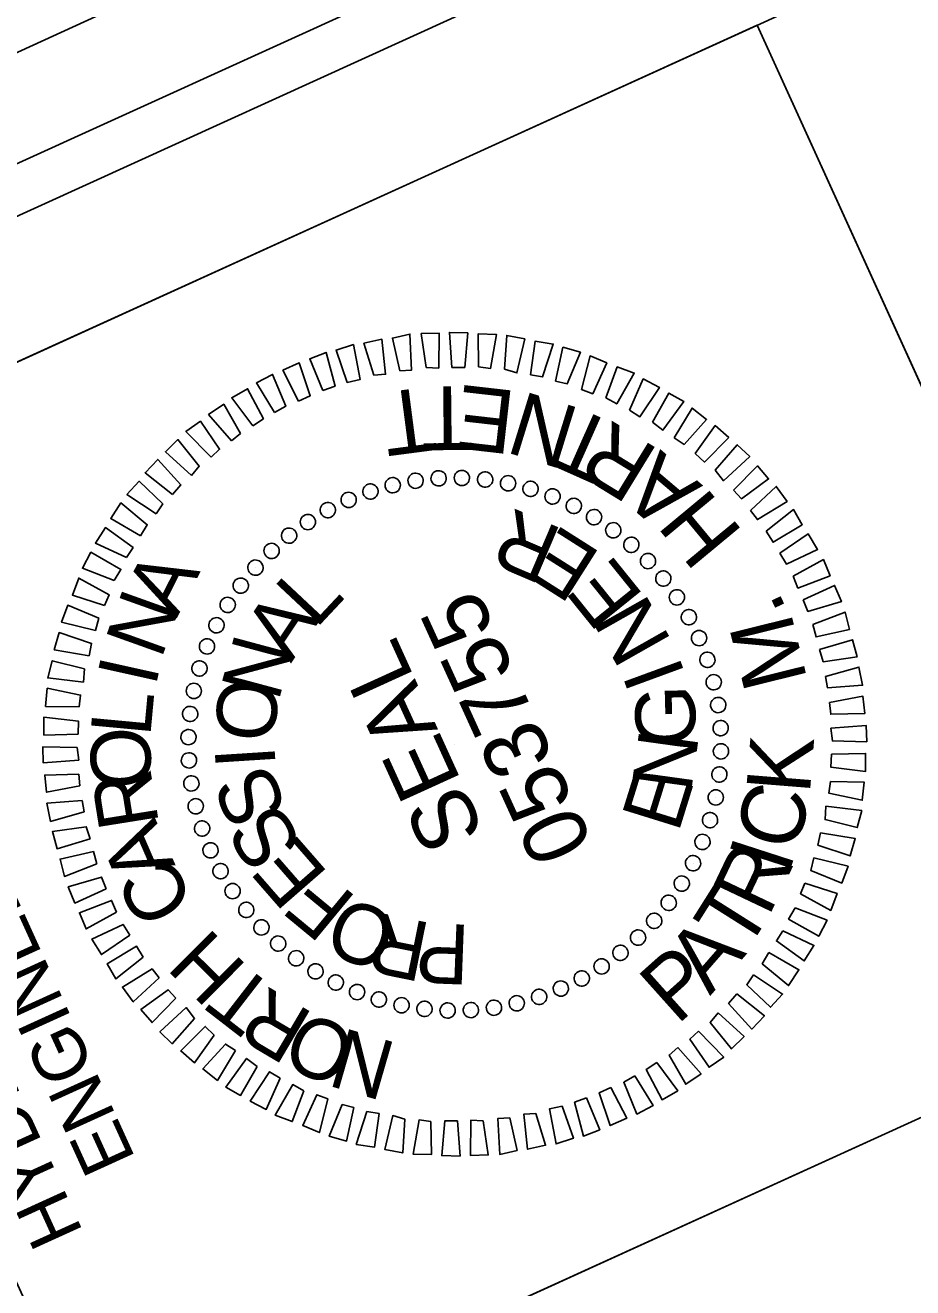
# Model space of a CAD drawing. Extents: x 2097304 to 2099003, y 683920 to 685908.
# Drawn here: x 2097390.4 to 2097474, y 685385.6 to 685504.5 of the extents above; entities that cross this region are included whole.
import ezdxf

# ---------------------------------------------------------------- set-up
doc = ezdxf.new("R2010")
doc.units = 0
for name, color, linetype in [('Sheet PE Seal Cell', 7, 'Continuous'), ('Sheet Plot Border Inside CELL', 7, 'Continuous'), ('Sheet Plot Border Outside CELL', 7, 'Continuous'), ('Sheet Profile CELL', 7, 'Continuous'), ('Sheet Sticker Exception Certification CELL', 7, 'Continuous'), ('Sheet Sticker Incomplete CELL', 7, 'Continuous')]:
    doc.layers.add(name, color=color, linetype=linetype)

msp = doc.modelspace()

# ---------------------------------------------------------------- linework, layer by layer
at = {"layer": 'Sheet PE Seal Cell'}
for p, q in [((2097427.17, 685461.63), (2097427.17, 685461.63)), ((2097429.37, 685461.86), (2097429.37, 685461.86)), ((2097431.56, 685461.87), (2097431.56, 685461.87)), ((2097433.75, 685461.77), (2097433.75, 685461.77)), ((2097435.91, 685461.38), (2097435.91, 685461.38)), ((2097422.97, 685460.6), (2097422.97, 685460.6)), ((2097425.07, 685461.17), (2097425.07, 685461.17)), ((2097438.06, 685460.87), (2097438.06, 685460.87)), ((2097440.09, 685460.15), (2097440.09, 685460.15)), ((2097418.92, 685458.87), (2097418.92, 685458.87)), ((2097420.91, 685459.82), (2097420.91, 685459.82)), ((2097442.14, 685459.27), (2097442.14, 685459.27)), ((2097417.09, 685457.7), (2097417.09, 685457.7)), ((2097444, 685458.19), (2097444, 685458.19)), ((2097445.84, 685456.94), (2097445.84, 685456.94)), ((2097415.25, 685456.43), (2097415.25, 685456.43)), ((2097447.56, 685455.58), (2097447.56, 685455.58)), ((2097413.59, 685455.01), (2097413.59, 685455.01)), ((2097412.1, 685453.46), (2097412.1, 685453.46)), ((2097449.11, 685454.09), (2097449.11, 685454.09)), ((2097410.74, 685451.74), (2097410.74, 685451.74)), ((2097450.53, 685452.43), (2097450.53, 685452.43)), ((2097451.8, 685450.59), (2097451.8, 685450.59)), ((2097409.49, 685449.9), (2097409.49, 685449.9)), ((2097452.97, 685448.76), (2097452.97, 685448.76)), ((2097408.41, 685448.04), (2097408.41, 685448.04)), ((2097407.53, 685445.99), (2097407.53, 685445.99)), ((2097453.92, 685446.78), (2097453.92, 685446.78)), ((2097454.7, 685444.71), (2097454.7, 685444.71)), ((2097406.81, 685443.96), (2097406.81, 685443.96)), ((2097455.27, 685442.61), (2097455.27, 685442.61)), ((2097406.31, 685441.81), (2097406.31, 685441.81)), ((2097455.73, 685440.51), (2097455.73, 685440.51)), ((2097405.91, 685439.65), (2097405.91, 685439.65)), ((2097455.96, 685438.31), (2097455.96, 685438.31)), ((2097405.81, 685437.46), (2097405.81, 685437.46)), ((2097430.89, 685436.79), (2097430.89, 685436.79)), ((2097405.82, 685435.27), (2097405.82, 685435.27)), ((2097455.97, 685436.12), (2097455.97, 685436.12)), ((2097455.87, 685433.93), (2097455.87, 685433.93)), ((2097406.05, 685433.07), (2097406.05, 685433.07)), ((2097455.48, 685431.77), (2097455.48, 685431.77)), ((2097406.51, 685430.97), (2097406.51, 685430.97)), ((2097454.97, 685429.62), (2097454.97, 685429.62)), ((2097407.08, 685428.87), (2097407.08, 685428.87)), ((2097407.86, 685426.81), (2097407.86, 685426.81)), ((2097454.25, 685427.59), (2097454.25, 685427.59)), ((2097408.82, 685424.82), (2097408.82, 685424.82)), ((2097453.37, 685425.54), (2097453.37, 685425.54)), ((2097452.29, 685423.68), (2097452.29, 685423.68)), ((2097409.98, 685422.99), (2097409.98, 685422.99)), ((2097411.25, 685421.15), (2097411.25, 685421.15)), ((2097451.04, 685421.84), (2097451.04, 685421.84)), ((2097449.68, 685420.13), (2097449.68, 685420.13)), ((2097412.67, 685419.49), (2097412.67, 685419.49)), ((2097448.19, 685418.57), (2097448.19, 685418.57)), ((2097414.23, 685418), (2097414.23, 685418)), ((2097415.95, 685416.64), (2097415.95, 685416.64)), ((2097446.53, 685417.15), (2097446.53, 685417.15)), ((2097417.78, 685415.39), (2097417.78, 685415.39)), ((2097444.69, 685415.88), (2097444.69, 685415.88)), ((2097419.64, 685414.31), (2097419.64, 685414.31)), ((2097440.88, 685413.76), (2097440.88, 685413.76)), ((2097442.86, 685414.72), (2097442.86, 685414.72)), ((2097421.69, 685413.43), (2097421.69, 685413.43)), ((2097423.72, 685412.71), (2097423.72, 685412.71)), ((2097438.81, 685412.98), (2097438.81, 685412.98)), ((2097425.87, 685412.21), (2097425.87, 685412.21)), ((2097428.03, 685411.81), (2097428.03, 685411.81)), ((2097430.22, 685411.71), (2097430.22, 685411.71)), ((2097432.41, 685411.72), (2097432.41, 685411.72)), ((2097434.61, 685411.95), (2097434.61, 685411.95)), ((2097436.71, 685412.41), (2097436.71, 685412.41))]:
    msp.add_line(p, q, dxfattribs=at)
for points in [[(2097428.21, 685472.27), (2097427.74, 685475.46), (2097429.42, 685475.51), (2097429.39, 685472.2)], [(2097430.62, 685472.27), (2097430.39, 685475.56), (2097432.11, 685475.52), (2097431.83, 685472.27)], [(2097420.77, 685470.86), (2097419.72, 685473.9), (2097421.35, 685474.42), (2097421.97, 685471.13)], [(2097423.26, 685471.55), (2097422.34, 685474.54), (2097424.03, 685474.92), (2097424.38, 685471.62)], [(2097425.71, 685471.95), (2097425.02, 685475.04), (2097426.67, 685475.41), (2097426.83, 685472.02)], [(2097433.13, 685472.31), (2097433.09, 685475.42), (2097434.81, 685475.38), (2097434.25, 685472.16)], [(2097435.59, 685472.11), (2097435.79, 685475.28), (2097437.48, 685474.95), (2097436.74, 685471.75)], [(2097438.03, 685471.57), (2097438.46, 685474.73), (2097440.17, 685474.47), (2097439.16, 685471.37)], [(2097418.48, 685470.09), (2097417.23, 685473.09), (2097418.77, 685473.69), (2097419.62, 685470.5)], [(2097440.38, 685470.99), (2097441.08, 685474.17), (2097442.72, 685473.7), (2097441.49, 685470.73)], [(2097442.83, 685470.19), (2097443.64, 685473.36), (2097445.21, 685472.69), (2097443.89, 685469.79)], [(2097416.19, 685469.1), (2097414.71, 685472), (2097416.25, 685472.7), (2097417.28, 685469.6)], [(2097445.11, 685469.41), (2097446.2, 685472.32), (2097447.79, 685471.73), (2097446.14, 685468.83)], [(2097413.93, 685468.02), (2097412.22, 685470.81), (2097413.73, 685471.61), (2097414.98, 685468.61)], [(2097447.35, 685468.23), (2097448.64, 685471.18), (2097450.16, 685470.39), (2097448.33, 685467.63)], [(2097411.87, 685466.76), (2097409.89, 685469.42), (2097411.38, 685470.26), (2097412.88, 685467.43)], [(2097449.5, 685467.12), (2097451.06, 685469.86), (2097452.46, 685469.07), (2097450.5, 685466.37)], [(2097409.88, 685465.35), (2097407.71, 685467.83), (2097409.13, 685468.8), (2097410.71, 685466.06)], [(2097451.55, 685465.64), (2097453.24, 685468.44), (2097454.61, 685467.36), (2097452.49, 685465.02)], [(2097407.94, 685463.81), (2097405.57, 685466.25), (2097406.94, 685467.2), (2097408.75, 685464.56)], [(2097453.53, 685464.18), (2097455.42, 685466.79), (2097456.7, 685465.67), (2097454.4, 685463.36)], [(2097406.09, 685462.09), (2097403.64, 685464.33), (2097404.82, 685465.47), (2097406.83, 685462.98)], [(2097455.4, 685462.61), (2097457.5, 685464.99), (2097458.67, 685463.88), (2097456.19, 685461.6)], [(2097404.32, 685460.3), (2097401.73, 685462.36), (2097402.92, 685463.61), (2097405.11, 685461.21)], [(2097457.14, 685460.71), (2097459.4, 685463), (2097460.45, 685461.78), (2097457.9, 685459.9)], [(2097402.78, 685458.5), (2097400.02, 685460.32), (2097401.17, 685461.55), (2097403.39, 685459.44)], [(2097458.73, 685458.8), (2097461.16, 685461.06), (2097462.18, 685459.65), (2097459.39, 685457.94)], [(2097401.31, 685456.4), (2097398.49, 685458.03), (2097399.46, 685459.51), (2097401.93, 685457.45)], [(2097460.22, 685456.84), (2097462.8, 685458.89), (2097463.62, 685457.45), (2097460.86, 685455.81)], [(2097399.99, 685454.37), (2097397.06, 685455.73), (2097397.99, 685457.19), (2097400.6, 685455.31)], [(2097461.49, 685454.78), (2097464.17, 685456.61), (2097465.06, 685455.14), (2097462.12, 685453.75)], [(2097398.83, 685452.2), (2097395.83, 685453.36), (2097396.63, 685454.87), (2097399.45, 685453.25)], [(2097462.75, 685452.61), (2097465.61, 685454.18), (2097466.24, 685452.66), (2097463.2, 685451.49)], [(2097397.92, 685449.86), (2097394.89, 685450.84), (2097395.48, 685452.43), (2097398.34, 685450.87)], [(2097463.7, 685450.4), (2097466.66, 685451.75), (2097467.3, 685450.23), (2097464.15, 685449.29)], [(2097397.07, 685447.49), (2097393.86, 685448.28), (2097394.45, 685449.87), (2097397.36, 685448.67)], [(2097464.6, 685448.06), (2097467.64, 685449.23), (2097468.05, 685447.6), (2097464.91, 685446.89)], [(2097396.45, 685445.12), (2097393.18, 685445.67), (2097393.64, 685447.31), (2097396.69, 685446.28)], [(2097465.23, 685445.71), (2097468.33, 685446.63), (2097468.78, 685445.02), (2097465.59, 685444.56)], [(2097395.93, 685442.64), (2097392.57, 685443.03), (2097392.98, 685444.65), (2097396.02, 685443.89)], [(2097465.79, 685443.17), (2097468.95, 685444.06), (2097469.29, 685442.34), (2097465.99, 685442.11)], [(2097395.51, 685440.3), (2097392.36, 685440.35), (2097392.51, 685442.07), (2097395.66, 685441.42)], [(2097466.19, 685440.71), (2097469.32, 685441.31), (2097469.51, 685439.7), (2097466.3, 685439.61)], [(2097395.42, 685437.73), (2097392.21, 685437.65), (2097392.21, 685439.35), (2097395.46, 685438.96)], [(2097466.3, 685438.29), (2097469.64, 685438.55), (2097469.68, 685437.03), (2097466.46, 685437.1)], [(2097395.48, 685435.29), (2097392.14, 685435.03), (2097392.11, 685436.56), (2097395.33, 685436.48)], [(2097466.37, 685435.85), (2097469.57, 685435.93), (2097469.58, 685434.23), (2097466.32, 685434.62)], [(2097395.6, 685432.87), (2097392.46, 685432.27), (2097392.28, 685433.89), (2097395.48, 685433.97)], [(2097466.27, 685433.28), (2097469.43, 685433.23), (2097469.27, 685431.51), (2097466.12, 685432.17)], [(2097396, 685430.42), (2097392.83, 685429.53), (2097392.49, 685431.24), (2097395.79, 685431.48)], [(2097465.85, 685430.95), (2097469.22, 685430.55), (2097468.8, 685428.94), (2097465.76, 685429.7)], [(2097396.55, 685427.87), (2097393.45, 685426.95), (2097393, 685428.56), (2097396.19, 685429.02)], [(2097465.34, 685428.46), (2097468.61, 685427.91), (2097468.14, 685426.28), (2097465.09, 685427.3)], [(2097397.18, 685425.52), (2097394.14, 685424.35), (2097393.73, 685425.98), (2097396.87, 685426.69)], [(2097464.71, 685426.09), (2097467.93, 685425.3), (2097467.33, 685423.71), (2097464.42, 685424.91)], [(2097398.08, 685423.18), (2097395.12, 685421.83), (2097394.49, 685423.36), (2097397.63, 685424.29)], [(2097463.86, 685423.72), (2097466.89, 685422.74), (2097466.3, 685421.15), (2097463.45, 685422.71)], [(2097399.03, 685420.98), (2097396.18, 685419.4), (2097395.54, 685420.92), (2097398.58, 685422.09)], [(2097462.95, 685421.39), (2097465.95, 685420.22), (2097465.16, 685418.71), (2097462.33, 685420.33)], [(2097400.29, 685418.8), (2097397.61, 685416.98), (2097396.72, 685418.44), (2097399.66, 685419.83)], [(2097461.8, 685419.21), (2097464.72, 685417.85), (2097463.8, 685416.39), (2097461.18, 685418.27)], [(2097401.56, 685416.74), (2097398.98, 685414.69), (2097398.16, 685416.13), (2097400.93, 685417.77)], [(2097460.47, 685417.18), (2097463.3, 685415.56), (2097462.33, 685414.07), (2097459.85, 685416.13)], [(2097403.06, 685414.79), (2097400.62, 685412.53), (2097399.6, 685413.93), (2097402.39, 685415.64)], [(2097459.01, 685415.09), (2097461.76, 685413.26), (2097460.62, 685412.03), (2097458.39, 685414.15)], [(2097404.64, 685412.87), (2097402.39, 685410.58), (2097401.34, 685411.81), (2097403.89, 685413.68)], [(2097457.46, 685413.29), (2097460.05, 685411.22), (2097458.86, 685409.97), (2097456.67, 685412.37)], [(2097406.38, 685410.97), (2097404.28, 685408.59), (2097403.12, 685409.7), (2097405.59, 685411.99)], [(2097455.7, 685411.49), (2097458.14, 685409.26), (2097456.96, 685408.11), (2097454.95, 685410.6)], [(2097408.25, 685409.4), (2097406.37, 685406.79), (2097405.09, 685407.91), (2097407.39, 685410.22)], [(2097453.84, 685409.77), (2097456.22, 685407.33), (2097454.84, 685406.38), (2097453.03, 685409.02)], [(2097410.23, 685407.94), (2097408.54, 685405.14), (2097407.17, 685406.22), (2097409.29, 685408.56)], [(2097451.91, 685408.23), (2097454.08, 685405.76), (2097452.65, 685404.78), (2097451.08, 685407.52)], [(2097412.28, 685406.46), (2097410.73, 685403.72), (2097409.33, 685404.51), (2097411.28, 685407.21)], [(2097449.91, 685406.83), (2097451.89, 685404.16), (2097450.41, 685403.32), (2097448.9, 685406.15)], [(2097414.44, 685405.35), (2097413.14, 685402.4), (2097411.63, 685403.19), (2097413.45, 685405.95)], [(2097447.85, 685405.56), (2097449.56, 685402.77), (2097448.05, 685401.97), (2097446.8, 685404.97)], [(2097416.67, 685404.17), (2097415.58, 685401.26), (2097413.99, 685401.86), (2097415.64, 685404.75)], [(2097445.59, 685404.48), (2097447.08, 685401.58), (2097445.53, 685400.88), (2097444.5, 685403.98)], [(2097418.95, 685403.4), (2097418.14, 685400.23), (2097416.58, 685400.89), (2097417.89, 685403.79)], [(2097443.3, 685403.49), (2097444.55, 685400.49), (2097443.01, 685399.9), (2097442.17, 685403.08)], [(2097421.4, 685402.59), (2097420.71, 685399.42), (2097419.07, 685399.88), (2097420.3, 685402.86)], [(2097423.76, 685402.01), (2097423.33, 685398.85), (2097421.61, 685399.11), (2097422.62, 685402.21)], [(2097426.2, 685401.48), (2097425.99, 685398.31), (2097424.3, 685398.64), (2097425.05, 685401.83)], [(2097438.52, 685402.03), (2097439.44, 685399.04), (2097437.75, 685398.66), (2097437.4, 685401.96)], [(2097441.01, 685402.72), (2097442.06, 685399.69), (2097440.43, 685399.16), (2097439.81, 685402.45)], [(2097428.65, 685401.27), (2097428.69, 685398.16), (2097426.97, 685398.2), (2097427.54, 685401.43)], [(2097431.16, 685401.32), (2097431.4, 685398.02), (2097429.67, 685398.06), (2097429.95, 685401.32)], [(2097433.58, 685401.32), (2097434.04, 685398.12), (2097432.36, 685398.07), (2097432.39, 685401.38)], [(2097436.07, 685401.63), (2097436.76, 685398.54), (2097435.12, 685398.17), (2097434.95, 685401.56)]]:
    msp.add_lwpolyline(points, close=True, dxfattribs=at)
for centre, major_axis in [((2097429.37, 685461.83), (-0.044, 0.719)), ((2097431.56, 685461.86), (0.019, 0.72)), ((2097433.75, 685461.71), (0.082, 0.715)), ((2097422.95, 685460.58), (-0.228, 0.683)), ((2097425.05, 685461.18), (-0.168, 0.7)), ((2097427.2, 685461.6), (-0.106, 0.712)), ((2097435.91, 685461.36), (0.144, 0.705)), ((2097438.03, 685460.83), (0.205, 0.69)), ((2097420.9, 685459.8), (-0.287, 0.66)), ((2097440.1, 685460.12), (0.264, 0.67)), ((2097418.94, 685458.84), (-0.343, 0.633)), ((2097442.1, 685459.23), (0.322, 0.644)), ((2097444.01, 685458.17), (0.377, 0.614)), ((2097417.06, 685457.71), (-0.397, 0.601)), ((2097445.82, 685456.94), (0.429, 0.579)), ((2097415.29, 685456.43), (-0.448, 0.564)), ((2097413.64, 685454.99), (-0.495, 0.523)), ((2097447.52, 685455.57), (0.477, 0.539)), ((2097412.12, 685453.42), (-0.539, 0.477)), ((2097449.09, 685454.04), (0.523, 0.495)), ((2097450.53, 685452.39), (0.564, 0.448)), ((2097410.74, 685451.72), (-0.579, 0.429)), ((2097409.51, 685449.91), (-0.614, 0.377)), ((2097451.81, 685450.62), (0.601, 0.397)), ((2097452.94, 685448.75), (0.633, 0.343)), ((2097408.45, 685447.99), (-0.644, 0.322)), ((2097453.9, 685446.78), (0.66, 0.287)), ((2097407.56, 685446), (-0.67, 0.264)), ((2097406.85, 685443.93), (-0.69, 0.205)), ((2097454.68, 685444.74), (0.683, 0.228)), ((2097455.28, 685442.63), (0.7, 0.168)), ((2097406.32, 685441.81), (-0.705, 0.144)), ((2097455.7, 685440.48), (0.712, 0.106)), ((2097405.97, 685439.64), (-0.715, 0.082)), ((2097455.93, 685438.31), (0.719, 0.044)), ((2097405.82, 685437.46), (-0.72, 0.019)), ((2097455.96, 685436.12), (0.72, -0.019)), ((2097405.86, 685435.27), (-0.719, -0.044)), ((2097455.81, 685433.94), (0.715, -0.082)), ((2097406.09, 685433.1), (-0.712, -0.106)), ((2097406.5, 685430.95), (-0.7, -0.168)), ((2097455.47, 685431.78), (0.705, -0.144)), ((2097454.93, 685429.65), (0.69, -0.205)), ((2097407.1, 685428.85), (-0.683, -0.228)), ((2097454.22, 685427.59), (0.67, -0.264)), ((2097407.89, 685426.8), (-0.66, -0.287)), ((2097408.84, 685424.84), (-0.633, -0.343)), ((2097453.33, 685425.59), (0.644, -0.322)), ((2097452.27, 685423.67), (0.614, -0.377)), ((2097409.97, 685422.96), (-0.601, -0.397)), ((2097451.04, 685421.86), (0.579, -0.429)), ((2097411.26, 685421.19), (-0.564, -0.448)), ((2097449.67, 685420.16), (0.539, -0.477)), ((2097412.69, 685419.54), (-0.523, -0.495)), ((2097414.26, 685418.02), (-0.477, -0.539)), ((2097448.15, 685418.59), (0.495, -0.523)), ((2097415.96, 685416.64), (-0.429, -0.579)), ((2097446.49, 685417.15), (0.448, -0.564)), ((2097417.78, 685415.41), (-0.377, -0.614)), ((2097444.72, 685415.87), (0.397, -0.601)), ((2097419.69, 685414.35), (-0.322, -0.644)), ((2097442.85, 685414.74), (0.343, -0.633)), ((2097421.69, 685413.46), (-0.264, -0.67)), ((2097438.84, 685413), (0.228, -0.683)), ((2097440.88, 685413.79), (0.287, -0.66)), ((2097423.75, 685412.75), (-0.205, -0.69)), ((2097425.88, 685412.22), (-0.144, -0.705)), ((2097428.04, 685411.87), (-0.082, -0.715)), ((2097434.58, 685411.98), (0.106, -0.712)), ((2097436.73, 685412.4), (0.168, -0.7)), ((2097430.22, 685411.72), (-0.019, -0.72)), ((2097432.41, 685411.76), (0.044, -0.719))]:
    msp.add_ellipse(centre, major_axis=major_axis, ratio=0.999708, dxfattribs=at)
at = {"layer": 'Sheet Plot Border Inside CELL'}
msp.add_lwpolyline([(2098977.25, 684378), (2098287.02, 685894.84), (2097326.67, 685457.85), (2098016.9, 683941)], close=True, dxfattribs=at)
at = {"layer": 'Sheet Plot Border Outside CELL'}
msp.add_lwpolyline([(2099003.07, 684375.47), (2098305.59, 685908.24), (2097304.38, 685452.65), (2098001.85, 683919.87)], close=True, dxfattribs=at)
at = {"layer": 'Sheet Profile CELL'}
msp.add_line((2097398.39, 685366.88), (2097500.74, 685413.46), dxfattribs=at)
for points in [[(2097334.17, 685447.53), (2097955.44, 684082.23), (2098911.14, 684517.12), (2098289.88, 685882.41)], [(2097398.39, 685366.88), (2097356.97, 685457.9), (2097459.37, 685504.5), (2097500.79, 685413.48)], [(2097439.83, 685275.82), (2097398.39, 685366.88), (2097500.79, 685413.48), (2097542.23, 685322.41)]]:
    msp.add_lwpolyline(points, close=True, dxfattribs=at)
at = {"layer": 'Sheet Sticker Exception Certification CELL'}
msp.add_line((2097542.23, 685322.41), (2097459.38, 685504.48), dxfattribs=at)
at = {"layer": 'Sheet Sticker Incomplete CELL'}
msp.add_lwpolyline([(2097397.1, 685505.3), (2097375.71, 685495.56), (2097314.83, 685629.36), (2097336.22, 685639.1)], close=True, dxfattribs=at)

# ---------------------------------------------------------------- texts
at = {"layer": 'Sheet PE Seal Cell'}
for s, height, rotation, p in [('T', 6, 187.4231, (2097428.61, 685470.48)), ('T', 6, 180.6229, (2097432.62, 685470.51)), ('E', 6, 173.5136, (2097436.78, 685470.04)), ('N', 6, 162.7877, (2097442.86, 685468.36)), ('T', 6, 155.9875, (2097446.52, 685466.72)), ('R', 6, 148.5072, (2097450.28, 685464.44)), ('A', 6, 139.6669, (2097454.3, 685461.13)), ('H', 6, 129.6829, (2097458.16, 685456.7)), ('R', 5.64, 156.9488, (2097441.21, 685456.98)), ('E', 5.64, 147.5915, (2097444.82, 685454.72)), ('E', 5.64, 128.8792, (2097448.79, 685450.7)), ('A', 5.64, 63.0846, (2097404.7, 685448.6)), ('L', 5.64, 46.8683, (2097417.79, 685447.59)), ('N', 5.64, 70.2863, (2097403.23, 685444.7)), ('053755', 5.998, 114.4674, (2097443.99, 685427.33)), ('N', 5.64, 119.5238, (2097451.38, 685446.45)), ('.', 6, 115.4488, (2097462.22, 685449.38)), ('A', 5.64, 56.2277, (2097415.46, 685444.38)), ('M', 6, 103.9193, (2097464.11, 685442.87)), ('N', 5.64, 74.944, (2097414.28, 685440.71)), ('SEAL', 5.998, 114.4674, (2097433.76, 685428.43)), ('I', 5.64, 77.4876, (2097402.71, 685442.1)), ('I', 5.64, 110.1686, (2097452.63, 685443.33)), ('O', 5.64, 84.3009, (2097413.84, 685436.83)), ('L', 5.64, 84.6883, (2097402.21, 685437.42)), ('G', 5.64, 91.4577, (2097453.62, 685436.59)), ('O', 5.64, 91.8886, (2097402.35, 685432.65)), ('N', 5.64, 82.1014, (2097453.14, 685432.19)), ('K', 6, 85.435, (2097464.32, 685432.02)), ('I', 5.64, 93.657, (2097414.03, 685434.72)), ('R', 5.64, 99.0885, (2097403.05, 685429.29)), ('S', 5.64, 112.3678, (2097415.18, 685430.52)), ('E', 5.64, 72.7443, (2097451.93, 685428.35)), ('C', 6, 75.8529, (2097463.06, 685426.53)), ('S', 5.64, 121.723, (2097416.71, 685427.26)), ('A', 5.64, 113.4877, (2097404.61, 685425.38)), ('E', 5.64, 131.0785, (2097419.1, 685424.56)), ('R', 6, 64.5707, (2097460.43, 685420.43)), ('I', 6, 72.0509, (2097462.31, 685424.42)), ('C', 5.64, 120.6873, (2097406.52, 685421.91)), ('T', 6, 57.7704, (2097458.28, 685417.05)), ('F', 5.64, 140.4344, (2097421.79, 685422.27)), ('O', 5.64, 159.1487, (2097425.84, 685420.49)), ('R', 5.64, 168.5071, (2097428.8, 685419.91)), ('P', 5.64, 177.8663, (2097432.37, 685419.78)), ('H', 5.64, 135.0869, (2097411.48, 685415.82)), ('A', 6, 48.9301, (2097454.93, 685413.07)), ('P', 6, 41.8208, (2097451.81, 685410.28)), ('T', 5.64, 142.2872, (2097414.33, 685413.55)), ('R', 5.64, 149.4879, (2097417.74, 685411.36)), ('O', 5.64, 156.6892, (2097421.99, 685409.51)), ('N', 5.64, 163.8909, (2097425.59, 685408.61))]:
    msp.add_text(s, height=height, rotation=rotation, dxfattribs=at).set_placement(p)
at = {"layer": 'Sheet Profile CELL'}
for s, p in [('HYDRAULICS', (2097395.94, 685390.83)), ('ENGINEER', (2097400.87, 685397.74))]:
    msp.add_text(s, height=5, rotation=114.4674, dxfattribs=at).set_placement(p)

doc.saveas('drawing.dxf')
